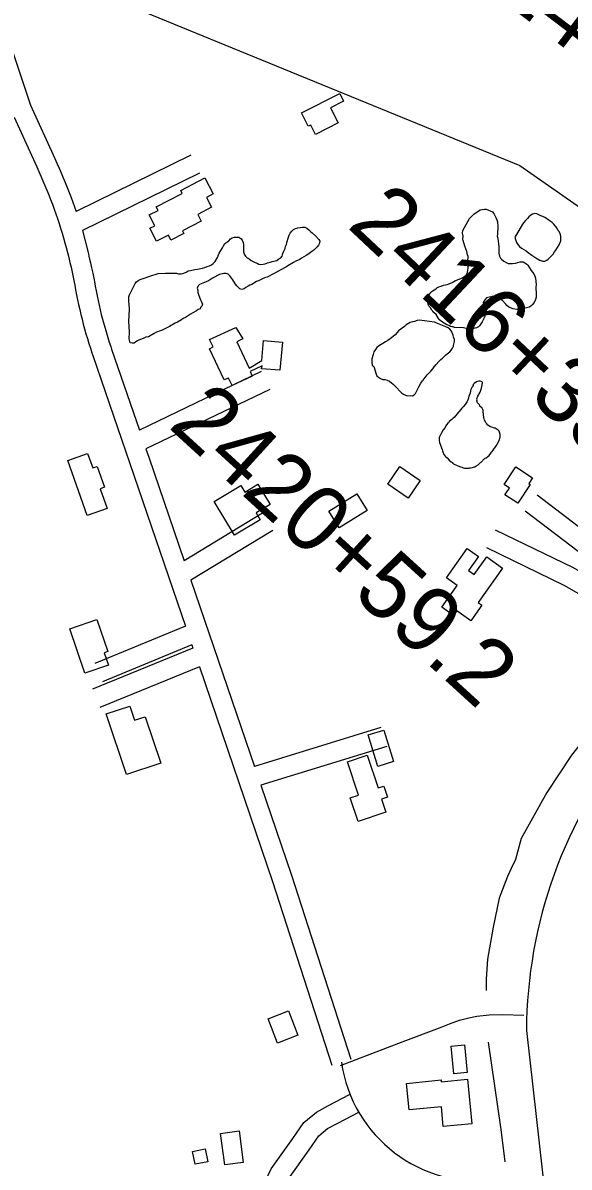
# Model space of a CAD drawing. Extents: x 3250478 to 3288318, y 788638 to 816472.
# Drawn here: x 3271685 to 3272509, y 795929 to 797655 of the extents above; entities that cross this region are included whole.
import ezdxf

# ---------------------------------------------------------------- set-up
doc = ezdxf.new("R2010")
doc.units = 0
for name, color, linetype in [('V-BLDG-OTLN', 7, 'Continuous'), ('V-ROAD-CNTR', 7, 'Continuous'), ('V-SITE-VEGE', 7, 'Continuous'), ('V-SURV-IDEN', 7, 'Continuous'), ('V-TOPO-SHOR', 7, 'Continuous'), ('V-UTIL-LINE', 7, 'Continuous')]:
    doc.layers.add(name, color=color, linetype=linetype)

msp = doc.modelspace()

# ---------------------------------------------------------------- linework, layer by layer
at = {"layer": 'V-BLDG-OTLN'}
for points in [[(3272126.3, 797486.3), (3272119, 797500.6), (3272115.3, 797498.7), (3272105.1, 797518.8), (3272162.8, 797548.1), (3272168.7, 797536.5), (3272149, 797526.5), (3272160.6, 797503.8)], [(3271922.9, 797402), (3271959.5, 797420.8), (3271971.9, 797396.7), (3271961.9, 797391.6), (3271969.6, 797376.6), (3271948.6, 797365.8), (3271953.8, 797355.7), (3271925.6, 797341.2), (3271927.8, 797336.9), (3271908.2, 797326.8), (3271904.3, 797334.5), (3271886.6, 797325.4), (3271876.6, 797345), (3271883.8, 797348.7), (3271875.4, 797365.1), (3271888.9, 797372), (3271886.1, 797377.4), (3271925.2, 797397.5)], [(3271966.6, 797163.4), (3271971.9, 797166.1), (3271966.2, 797177.1), (3272006.2, 797195.5), (3272016.5, 797178.1), (3272007.7, 797173.6), (3272026.1, 797134.2), (3272045.1, 797145.5), (3272047.8, 797176), (3272076.3, 797173.5), (3272072.6, 797130.8), (3272044.7, 797133.2), (3272045.7, 797137.7), (3272027.5, 797128.8), (3272030.9, 797122.1), (3272000.6, 797108), (3271994.9, 797119.2), (3271988.5, 797116.4)], [(3271752.5, 796994.6), (3271782.6, 797005.3), (3271790.3, 796983.6), (3271796.7, 796985.8), (3271807.9, 796954.4), (3271801.4, 796952.1), (3271812, 796922.4), (3271782, 796911.8)], [(3272284.3, 796964.7), (3272266.3, 796938.3), (3272235.6, 796959.2), (3272253.6, 796985.7)], [(3272453.7, 796968.8), (3272447.9, 796960.1), (3272450.3, 796958.5), (3272431.7, 796930.4), (3272412.1, 796943.3), (3272418.7, 796953.2), (3272410.7, 796958.5), (3272428.6, 796985.5)], [(3272043, 796905.6), (3272004.2, 796882.1), (3271973.5, 796932.9), (3272013.6, 796957.1), (3272019.5, 796947.2), (3272039.1, 796959.1), (3272057.7, 796928.4), (3272036.8, 796915.8)], [(3272146.6, 796918.5), (3272188.6, 796944.4), (3272204.1, 796919.3), (3272162.1, 796893.4)], [(3272408.5, 796832.7), (3272371.5, 796780.9), (3272377.3, 796776.8), (3272360.4, 796753.1), (3272339.4, 796768), (3272334.6, 796761.3), (3272317, 796773.9), (3272340.1, 796806.3), (3272323.7, 796818), (3272355.2, 796862.3), (3272372.1, 796850.3), (3272356.9, 796829), (3272365.5, 796822.9), (3272384.7, 796849.7)], [(3271796.3, 796755.1), (3271812.9, 796706.9), (3271807.7, 796705.1), (3271814.1, 796686.4), (3271778.5, 796674.2), (3271755.5, 796741)], [(3271810.5, 796612.7), (3271846.2, 796624.7), (3271853.5, 796603.1), (3271869.3, 796608.4), (3271892.8, 796538.6), (3271841.4, 796521.2)], [(3272220.4, 796533.4), (3272205.5, 796581.1), (3272229.1, 796588.5), (3272244, 796540.8)], [(3272190.6, 796450.5), (3272178.7, 796486.1), (3272191.2, 796490.3), (3272174.3, 796540.5), (3272204.2, 796550.6), (3272220.9, 796501.1), (3272229.3, 796504), (3272234.8, 796487.5), (3272225.6, 796484.4), (3272232.3, 796464.5)], [(3272068.8, 796116.5), (3272054.8, 796153.1), (3272085.8, 796164.9), (3272099.8, 796128.3)], [(3272335, 796069.9), (3272330.8, 796111.9), (3272350.9, 796113.9), (3272355.1, 796071.9)], [(3272355.6, 796061.9), (3272362.2, 795994.8), (3272319, 795990.6), (3272316.1, 796020.6), (3272267.5, 796015.8), (3272263.5, 796055.7), (3272315.7, 796060.9), (3272316, 796057.9)], [(3271989.5, 795932.7), (3271983, 795980.2), (3272010.9, 795984), (3272017.4, 795936.6)], [(3271944.9, 795933.7), (3271940.9, 795953.1), (3271960.1, 795957), (3271964, 795937.6)]]:
    msp.add_lwpolyline(points, close=True, dxfattribs=at)
at = {"layer": 'V-ROAD-CNTR'}
for points in [[(3271491.1, 798145.5), (3271597, 797827.9), (3271696.2, 797530.8), (3271733, 797450)], [(3271671.6, 797512.5), (3271705.7, 797437.5)], [(3271938.2, 797455.1), (3271765.1, 797370.3)], [(3271705.8, 797437.4), (3271709, 797430.5), (3271712.1, 797423.5), (3271715.2, 797416.5), (3271718.2, 797409.5), (3271721.1, 797402.5), (3271723.9, 797395.4), (3271726.7, 797388.3), (3271729.4, 797381.1), (3271732, 797374), (3271734.6, 797366.8), (3271737, 797359.6), (3271739.4, 797352.4), (3271741.8, 797345.1), (3271744, 797337.8), (3271746.2, 797330.5), (3271748.3, 797323.2), (3271750.3, 797315.8), (3271752.3, 797308.4), (3271754.1, 797301.1), (3271755.9, 797293.6), (3271757.6, 797286.2), (3271759.3, 797278.8), (3271760.8, 797271.3), (3271762.3, 797263.8), (3271763.2, 797259.3)], [(3271733, 797450), (3271736.3, 797442.9), (3271739.6, 797435.7), (3271742.7, 797428.4), (3271745.8, 797421.1), (3271748.9, 797413.8), (3271751.8, 797406.4), (3271754.7, 797399), (3271757.5, 797391.6), (3271760.2, 797384.2), (3271765.1, 797370.3)], [(3271951.4, 797428.1), (3271774.8, 797341.7)], [(3271774.8, 797341.7), (3271783.2, 797308.3), (3271785.1, 797300.6), (3271786.9, 797292.8), (3271788.6, 797285.1), (3271790.2, 797277.3), (3271791.8, 797269.6), (3271792.7, 797264.9)], [(3271792.7, 797264.7), (3271794, 797257.5), (3271795.3, 797250.4), (3271796.8, 797243.3), (3271798.3, 797236.2), (3271799.8, 797229.2), (3271801.5, 797222.2), (3271803.2, 797215.1), (3271805, 797208.1), (3271806.9, 797201.1), (3271808.9, 797194.2), (3271810.9, 797187.2), (3271813, 797180.3), (3271815.2, 797173.4), (3271817.5, 797166.5), (3271818.7, 797162.8)], [(3271763.2, 797259.4), (3271764.5, 797252.1), (3271765.9, 797244.7), (3271767.4, 797237.3), (3271769, 797229.9), (3271770.6, 797222.5), (3271772.3, 797215.1), (3271774.1, 797207.8), (3271776, 797200.5), (3271778, 797193.2), (3271780, 797185.9), (3271782.2, 797178.7), (3271784.4, 797171.4), (3271786.7, 797164.2), (3271789, 797157.1), (3271790.3, 797153.2)], [(3271818.7, 797162.8), (3271860.7, 797040.8)], [(3271790.4, 797153.1), (3271846.4, 796990.2), (3271930.1, 796745.3)], [(3272044.1, 797129.1), (3271860.7, 797040.8)], [(3272057.2, 797102.1), (3271870.5, 797012.3)], [(3271870.5, 797012.3), (3271874.8, 796999.9), (3271928.2, 796843.5)], [(3272734.8, 796742.3), (3272586.5, 796846.5), (3272460.8, 796942.4)], [(3272717.5, 796717.7), (3272568.7, 796822.3), (3272442.6, 796918.6)], [(3272046.3, 796915.2), (3271928.2, 796843.5)], [(3272061.8, 796889.5), (3271938.1, 796814.5)], [(3272707.7, 796707.3), (3272662.8, 796742.9), (3272588.4, 796791.1), (3272515.6, 796833), (3272397.9, 796890)], [(3272689, 796683.8), (3272645.3, 796718.5), (3272572.8, 796765.5), (3272501.5, 796806.5), (3272384.8, 796863)], [(3271938.1, 796814.5), (3272034.1, 796533.6)], [(3271930.1, 796745.3), (3271793.3, 796688.8)], [(3271941.4, 796712.1), (3271789.9, 796650.3)], [(3271939.8, 796716.9), (3271804.8, 796661.1)], [(3271939.8, 796716.9), (3271941.4, 796712.1)], [(3271951.2, 796683.6), (3271801.2, 796622.5)], [(3271951.2, 796683.6), (3272061.6, 796360.3), (3272151, 796083)], [(3272224.9, 796592.1), (3272034.1, 796533.6)], [(3272233.7, 796563.4), (3272043.8, 796505.2)], [(3272043.8, 796505.2), (3272090.1, 796369.8), (3272179.5, 796092.2)], [(3272164.1, 796082.7), (3272258.7, 796118.9), (3272313.5, 796139.4), (3272328.4, 796145.6), (3272343.4, 796150.9), (3272357.5, 796154.7), (3272369.6, 796157), (3272388.1, 796158.9), (3272408.9, 796159.6), (3272440.7, 796158.5)], [(3272444.4, 796135.4), (3272482.6, 795795.7), (3272494, 795717.5)], [(3272109, 795614), (3272054.6, 795722.8), (3272042.9, 795765.3), (3272032.3, 795842.1), (3272042.4, 795890.7), (3272059.6, 795927.1), (3272092, 795972.6), (3272108.9, 795996.8), (3272127.6, 796012.5), (3272145.8, 796022.4), (3272177.5, 796038.9)], [(3272135.8, 795627.4), (3272082.8, 795733.6), (3272072.3, 795771.4), (3272062.7, 795841), (3272071, 795881.1), (3272085.6, 795911.9), (3272116.5, 795955.3), (3272131.2, 795976.4), (3272144.6, 795987.5), (3272159.9, 795995.9), (3272191.4, 796012.3)]]:
    msp.add_lwpolyline(points, dxfattribs=at)
for centre, radius, start, end in [((3273149.6, 796131.6), 705.2, 140.6482, 179.6985), ((3272372.3, 796117.6), 209.2, 188.2379, 277.1118)]:
    msp.add_arc(centre, radius, start, end, dxfattribs=at)
at = {"layer": 'V-SITE-VEGE'}
for points in [[(3272348.3, 797341.4), (3272358.7, 797359.8), (3272359.9, 797361.4), (3272361.6, 797362.5), (3272362.9, 797364.1), (3272365, 797366.1), (3272374.5, 797372.7), (3272377.8, 797373.4), (3272381, 797373.7), (3272383.5, 797373.6), (3272393.1, 797369.6), (3272394.2, 797368), (3272395.8, 797366.3), (3272398.5, 797361.3), (3272399.6, 797357.6), (3272400.7, 797354.8), (3272401.3, 797347.8), (3272400.9, 797336.1), (3272400.4, 797332.9), (3272401.1, 797330), (3272401.8, 797325.1), (3272402.5, 797321.8), (3272402.7, 797316.5), (3272402.6, 797313.3), (3272402.9, 797307.6), (3272403.9, 797303.1), (3272405.5, 797299.8), (3272406.6, 797298.2), (3272410.2, 797295.2), (3272417, 797292.1), (3272423.5, 797291.9), (3272427.9, 797292.6)], [(3272427.9, 797292.6), (3272434.9, 797294.4), (3272439.4, 797294.3), (3272441.8, 797293), (3272444.9, 797290.8), (3272446.5, 797289.2), (3272451.5, 797281.3), (3272455.4, 797276.3), (3272457, 797273), (3272458.1, 797269.7), (3272459, 797260.3), (3272458.8, 797256.3), (3272459.3, 797245.7), (3272459.2, 797240.9), (3272458.2, 797237.6), (3272456.1, 797233.2), (3272453.1, 797229.7), (3272451.5, 797228.1), (3272449, 797226.2), (3272440, 797224), (3272432.2, 797222.6), (3272429.8, 797222.7), (3272424.5, 797223.7), (3272418.1, 797225.9), (3272414.9, 797228.5), (3272413.4, 797230.6), (3272407.9, 797236.4), (3272406.7, 797238.1), (3272403.1, 797240.6), (3272400.4, 797242.3), (3272397.1, 797243.3), (3272384.4, 797240), (3272381.5, 797237.3), (3272379, 797233.3), (3272380, 797228.4), (3272380.3, 797225.5), (3272381, 797222.7), (3272381.6, 797214.1), (3272381.5, 797211.7), (3272378.5, 797206.1), (3272377.6, 797204.1), (3272373.8, 797197.7), (3272372.1, 797196.2), (3272369.2, 797195), (3272365.1, 797193.9), (3272361, 797193.3), (3272355.3, 797193.5), (3272349.7, 797194.8), (3272335.9, 797195.3), (3272333.9, 797196.2), (3272331.9, 797196.2), (3272329.9, 797197.1), (3272327.5, 797198.4), (3272324.3, 797199.3), (3272316.3, 797204.4), (3272313.2, 797207), (3272311.6, 797209.1), (3272308.1, 797214.9), (3272305, 797217.8), (3272303.4, 797219.9), (3272301.9, 797221.6), (3272299.5, 797224.9), (3272297.6, 797227), (3272296, 797229.9), (3272295, 797236.4), (3272295.2, 797240.8), (3272296.5, 797243.2), (3272296.9, 797243.6), (3272298.2, 797245.6), (3272300.7, 797248.4), (3272302.4, 797250), (3272304.9, 797251.5), (3272306.9, 797253.1), (3272309, 797254.2), (3272309.4, 797255), (3272312.3, 797256.5), (3272315.6, 797257.6), (3272319.3, 797259.2), (3272322.6, 797259.9), (3272325, 797260.2), (3272329.1, 797261.7), (3272332.4, 797263.2), (3272334.5, 797264.3), (3272336.6, 797265.9), (3272348.1, 797270), (3272350.6, 797272.4), (3272353.5, 797274.3), (3272354.8, 797276.3), (3272356.1, 797281.1), (3272356.7, 797285.1), (3272356.8, 797288.8), (3272356.2, 797294.9), (3272356.4, 797302.2), (3272355.7, 797304.7), (3272354.6, 797310), (3272351.6, 797317.8), (3272349.1, 797326.4), (3272348.7, 797328.4), (3272348.9, 797332.9), (3272348.2, 797337.4), (3272348.3, 797341.4)]]:
    msp.add_lwpolyline(points, dxfattribs=at)
at = {"layer": 'V-TOPO-SHOR'}
for points in [[(3272429.4, 797335.7), (3272427.6, 797332.7), (3272427.5, 797329.5), (3272428.3, 797326.4), (3272429.3, 797323.6), (3272431.3, 797320.3), (3272434.1, 797317.3), (3272437.2, 797314.9), (3272440.4, 797313.2), (3272443.8, 797311.2), (3272447.2, 797308.3), (3272452.7, 797304.6), (3272458.6, 797300.3), (3272464.8, 797296.9), (3272469.1, 797295.6), (3272472.1, 797295.5), (3272475, 797296.8), (3272477.4, 797298.6), (3272484.6, 797305.8), (3272486.9, 797309.4), (3272488.9, 797312.1), (3272493.7, 797319.8), (3272496.1, 797326), (3272496.4, 797329.6), (3272496.3, 797332.9), (3272495.3, 797336.4), (3272493.9, 797339.9), (3272492, 797342.3), (3272490.4, 797345.6), (3272485.8, 797351.4), (3272483.3, 797353.7), (3272477.4, 797357.5), (3272474.8, 797359.6), (3272472.1, 797361.2), (3272469.3, 797362.6), (3272466.1, 797363.8), (3272462.9, 797365.4), (3272460.1, 797366.6), (3272456.9, 797367.1), (3272453.6, 797366.1), (3272451, 797364.7), (3272448.3, 797362.4), (3272446, 797359.9), (3272442.9, 797356.7), (3272440.6, 797353.7), (3272438.4, 797351.2), (3272429.4, 797335.7)], [(3271846.7, 797172), (3271845.1, 797178.2), (3271845.5, 797188.3), (3271844.9, 797204.8), (3271845.5, 797222.3), (3271845.3, 797230.8), (3271844.8, 797233.8), (3271844.8, 797241.4), (3271845.8, 797244.6), (3271849, 797251.9), (3271854.3, 797261.7), (3271856.1, 797264.2), (3271858.6, 797266.1), (3271861.7, 797267.7), (3271865, 797268.5), (3271880.9, 797274.3), (3271884.5, 797275.4), (3271888.8, 797276.6), (3271900.1, 797277.5), (3271909.6, 797277.2), (3271913.1, 797277.3), (3271916.4, 797277.2), (3271919.8, 797276.5), (3271923.9, 797276.1), (3271927.6, 797277.1), (3271931.1, 797278.7), (3271934.4, 797280.6), (3271937.5, 797281.5), (3271944.3, 797282.8), (3271948.4, 797283.4), (3271955.8, 797284.6), (3271959.3, 797285.6), (3271962.8, 797287.2), (3271966.5, 797288.4), (3271969.6, 797290), (3271972.1, 797292.1), (3271974.8, 797295.1), (3271978.4, 797301), (3271981, 797307.2), (3271986, 797315.7), (3271987.4, 797318.7), (3271989.7, 797322.1), (3271995.5, 797326.2), (3271998.2, 797328.8), (3272000.8, 797330.4), (3272003.9, 797331.6), (3272007.3, 797331.5), (3272010.6, 797331.6), (3272013.8, 797329.6), (3272015.6, 797326.9), (3272017, 797323.4), (3272017.6, 797319.9), (3272017.9, 797316.6), (3272017.8, 797312.5), (3272017.9, 797309.3), (3272018.6, 797305.8), (3272020.7, 797302.9), (3272023.2, 797300.4), (3272026.2, 797298.8), (3272029.2, 797296.6), (3272035.1, 797293.3), (3272038.4, 797292.6), (3272040.9, 797291), (3272043.9, 797290.5), (3272047.2, 797290.8), (3272050.5, 797291.6), (3272054, 797293), (3272057.9, 797293.9), (3272061, 797295.1), (3272067.9, 797296.4), (3272071.1, 797298.7), (3272074.1, 797300.5), (3272076, 797303.1), (3272077.2, 797306.7), (3272078.6, 797310.4), (3272080.4, 797314.4)], [(3272080.4, 797314.4), (3272081.2, 797317.6), (3272082.4, 797320.4), (3272083.1, 797323.6), (3272085.3, 797331.4), (3272086.5, 797334.6), (3272088.1, 797337.4), (3272090.4, 797340.5), (3272093.1, 797343.3), (3272096.1, 797344.5), (3272099.4, 797345.4), (3272103.1, 797346.2), (3272106.8, 797346.7), (3272110.1, 797346.4), (3272113, 797345), (3272116, 797342.7), (3272118.5, 797340.3), (3272121.3, 797338), (3272127, 797332.9), (3272131.1, 797328.2), (3272132.8, 797325.3), (3272132.5, 797322.3), (3272130.9, 797319.3), (3272129, 797316.8), (3272123.9, 797312.2), (3272120.8, 797309.7), (3272114.6, 797305.5), (3272112, 797304.1), (3272108.6, 797301.8), (3272105.3, 797300), (3272102.4, 797298.1), (3272096.7, 797295.5), (3272093.2, 797293.2), (3272084.6, 797288.5), (3272081.3, 797286.4), (3272072.9, 797282), (3272063, 797276.2), (3272053.3, 797271.3), (3272049.3, 797270.1), (3272046.3, 797268.5), (3272040.5, 797265.9), (3272037.3, 797264.7), (3272030.4, 797260.4), (3272027.1, 797259.2), (3272024.5, 797257.7), (3272021.1, 797255.7), (3272018.5, 797253.6), (3272015, 797252.6), (3272012.2, 797253.8), (3272009.9, 797255.8), (3272007.8, 797258.1), (3272005.7, 797260.9), (3272001.8, 797267.1), (3271997, 797273.3), (3271994.7, 797275.6), (3271991.5, 797276.8), (3271988.2, 797276.7), (3271981.5, 797275.1), (3271970.9, 797269.9), (3271964.9, 797265.9), (3271961.4, 797264.1), (3271958.6, 797263.1), (3271951.5, 797260.1), (3271949.1, 797258.2), (3271947.9, 797254.8), (3271948.7, 797251.5), (3271949, 797248), (3271950, 797245), (3271951.4, 797241), (3271953, 797237.1), (3271954.4, 797234.2), (3271955.8, 797230.7), (3271955, 797227.7), (3271952.8, 797225.6), (3271952.3, 797223.7), (3271949.5, 797222.5), (3271946.6, 797220.6), (3271941.1, 797217.5), (3271937.6, 797215.4), (3271930.4, 797210.3), (3271926.5, 797208.7), (3271924.1, 797206.8), (3271918.1, 797203.3), (3271914.8, 797201.9), (3271906, 797196.8), (3271901.8, 797195), (3271895, 797191.5), (3271891.9, 797190.5), (3271886.2, 797188.1), (3271882.9, 797186.5), (3271877.1, 797183), (3271874.3, 797181.5), (3271870.6, 797180.6), (3271867.5, 797179.4), (3271864, 797177.8), (3271860.7, 797177), (3271858, 797175.1), (3271855.4, 797173.7), (3271852.7, 797171.8), (3271849.7, 797171.5), (3271846.7, 797172)], [(3272217.8, 797125.2), (3272219, 797122.4), (3272221.3, 797120.4), (3272224.3, 797118.3), (3272227.7, 797117.1), (3272230.7, 797116.8), (3272234.4, 797116), (3272237.8, 797114.2), (3272240.9, 797111.9), (3272243.2, 797109.7), (3272246.4, 797107), (3272256.1, 797097.1), (3272258.8, 797094.9), (3272261.8, 797093.3), (3272264.8, 797092.3), (3272269.3, 797092.6), (3272272.4, 797092.3), (3272275, 797093.7), (3272277.2, 797095.8), (3272282.3, 797106), (3272285.3, 797111.4), (3272287.8, 797115), (3272288.9, 797116), (3272294.8, 797123.8), (3272300.4, 797129.7), (3272303.4, 797133.1), (3272305.4, 797136.1), (3272308.1, 797139.4), (3272312.4, 797144.3), (3272315.1, 797147), (3272317.7, 797149.1), (3272323.1, 797154.1), (3272328.7, 797158.7), (3272330.9, 797161), (3272333, 797164.4), (3272334.4, 797167.4), (3272334.4, 797168.1), (3272335.9, 797174.1), (3272335.8, 797177.3), (3272334.6, 797180.6), (3272333.8, 797183.7), (3272331.2, 797189.8), (3272329.1, 797192.9), (3272326.6, 797194.7), (3272322.9, 797196.4), (3272310.5, 797201.5), (3272306, 797203.2), (3272298.3, 797204.5), (3272283, 797206.3), (3272279.7, 797206), (3272275.5, 797204.6), (3272272.5, 797204.1), (3272269, 797202.7), (3272263, 797199.4), (3272260.4, 797197.1), (3272251.7, 797190.2), (3272249.7, 797187.9), (3272246.3, 797184.5), (3272240.7, 797179.7), (3272235.4, 797176), (3272231.9, 797174), (3272221.1, 797167.2), (3272218.8, 797165.1), (3272216.6, 797162.1), (3272214.3, 797158.5), (3272213.1, 797154.8), (3272211.3, 797148.2), (3272211, 797145.2), (3272211.1, 797141.9), (3272211.7, 797138.6), (3272214.2, 797136.6), (3272217.8, 797125.2)], [(3272389.2, 797046.3), (3272387.9, 797047), (3272386, 797048.3), (3272384.5, 797049.9), (3272383.9, 797051.2), (3272383.1, 797052.3), (3272381.4, 797055.6), (3272380.9, 797057.6), (3272380.3, 797058.9), (3272379.6, 797065.4), (3272379.2, 797067.6), (3272379.3, 797070.2), (3272378.9, 797071.5), (3272377.7, 797073.5), (3272374.3, 797076.9), (3272373.5, 797078.6), (3272370.8, 797081.8), (3272370, 797083.5), (3272369.8, 797084.8), (3272369.9, 797086.3), (3272369.5, 797087.9), (3272371.1, 797091.7), (3272374.6, 797097.9), (3272376.7, 797103.7), (3272377.5, 797108.6), (3272377.6, 797109.7), (3272378.3, 797111.4), (3272378.3, 797112.5), (3272377.7, 797113.4), (3272376.4, 797114.1), (3272374.9, 797114.5), (3272373.6, 797114.6), (3272372.5, 797114.4), (3272369, 797113.2), (3272365.7, 797110.7), (3272364.3, 797109.3), (3272363.9, 797108), (3272362.7, 797106.1), (3272360.6, 797101.8), (3272360.1, 797099.9), (3272359.6, 797096.6), (3272357.7, 797091.7), (3272356.5, 797087.2), (3272354.9, 797084), (3272351.9, 797079.1), (3272349.2, 797075.7), (3272346.9, 797073.6), (3272342.9, 797068.8), (3272341.8, 797067.7), (3272335.2, 797059.5), (3272334.1, 797058.9), (3272331.9, 797056.8), (3272327.9, 797053.5), (3272326.7, 797051.5), (3272325.6, 797050.7), (3272322.9, 797047.1), (3272321.7, 797044.8), (3272319, 797041), (3272315.8, 797035.7), (3272313.5, 797030.7), (3272313, 797029.2), (3272312.7, 797027.5), (3272312.7, 797025.1), (3272313.2, 797021.9), (3272317.2, 797011.3), (3272317.6, 797009.6), (3272320, 797004.1), (3272322.5, 797001), (3272324.8, 796998.8), (3272327.7, 796995.2), (3272330.7, 796992.7), (3272332.8, 796991.6), (3272333.6, 796990.5), (3272336.4, 796988.8), (3272339, 796987.7), (3272343.7, 796986), (3272345.2, 796985.1), (3272346.9, 796984.6), (3272349, 796983.7), (3272351.2, 796983.2), (3272355.1, 796983.1), (3272356.4, 796983.4), (3272357.9, 796983.4), (3272359, 796984), (3272360.3, 796984), (3272362.9, 796984.3), (3272365.8, 796985.3), (3272366.8, 796985.5), (3272368.2, 796986.1), (3272371.5, 796988.4), (3272373.9, 796990.5), (3272375.1, 796991.9), (3272376.2, 796992.3), (3272377.1, 796993.2), (3272378.6, 796994.9), (3272379.3, 796995.9), (3272380.2, 796996.8), (3272381.3, 796997.4), (3272382.2, 796998.4), (3272383.7, 796999), (3272386.4, 797000.9)], [(3272386.4, 797000.9), (3272388, 797002.4), (3272390.9, 797005.7), (3272392, 797007.4), (3272392.9, 797008.3), (3272394.3, 797010.2), (3272396.3, 797013.6), (3272398.4, 797016.1), (3272399.8, 797018.7), (3272400.4, 797019.5), (3272403.9, 797025.9), (3272404.7, 797030.6), (3272404.8, 797034.1), (3272404, 797037.6), (3272403.2, 797039.1), (3272402, 797040.7), (3272400.5, 797041.8), (3272398.8, 797042.5), (3272397.3, 797043.4), (3272396.2, 797043.7), (3272390.9, 797045.8), (3272389.2, 797046.3)], [(3272637.9, 796702), (3272552.1, 796600.9), (3272512.4, 796550.6), (3272475.2, 796494.5), (3272436.4, 796425), (3272427.8, 796393.1), (3272421.3, 796379.5), (3272415.9, 796367.4), (3272403.5, 796334.9), (3272394.2, 796291.3), (3272385.5, 796242.8), (3272383.8, 796213), (3272383.8, 796195.9)], [(3272386.8, 796117.7), (3272405.9, 795986), (3272412, 795937.2)]]:
    msp.add_lwpolyline(points, dxfattribs=at)
at = {"layer": 'V-UTIL-LINE'}
msp.add_lwpolyline([(3271779.1, 797708), (3272434.5, 797439.4), (3273094.7, 796979.4), (3273232.3, 796851.7), (3274234.6, 796227.9)], dxfattribs=at)

# ---------------------------------------------------------------- texts
at = {"layer": 'V-SURV-IDEN'}
for s, rotation, p in [('2411+95.3', 322.8286, (3272395.3, 797697.1)), ('2416+35.2', 316.8308, (3272172.2, 797347.6)), ('2420+59.2', 317.6409, (3271902.4, 797045.9))]:
    msp.add_text(s, height=100, rotation=rotation, dxfattribs=at).set_placement(p)

doc.saveas('drawing.dxf')
